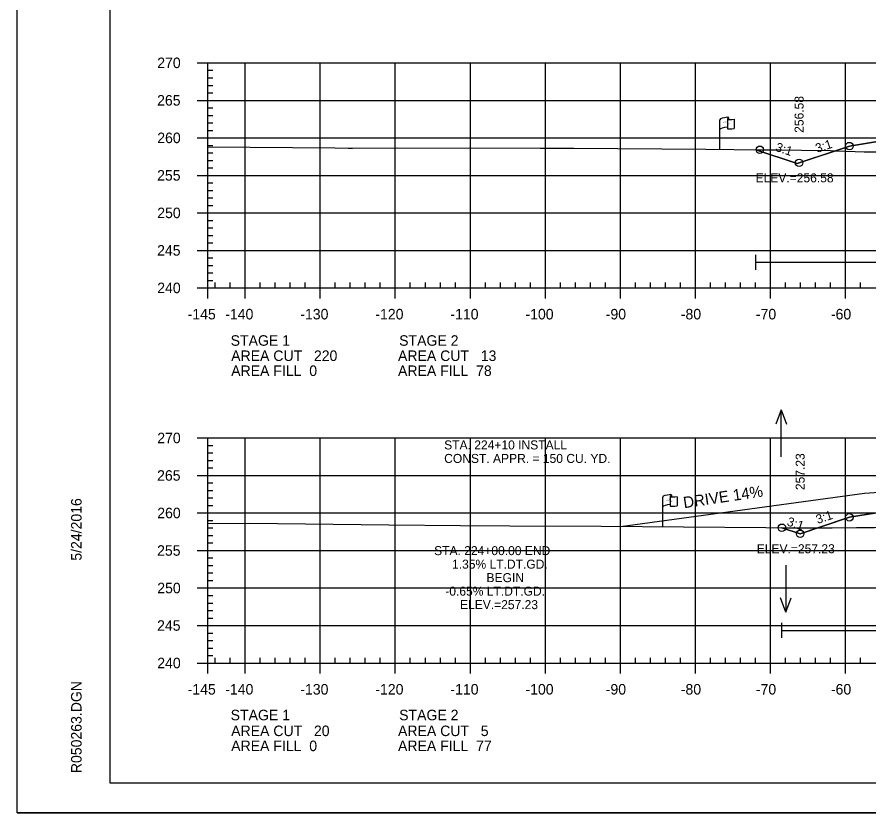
# Model space of a CAD drawing. Extents: x 1365647 to 1367999, y 387113 to 400173.
# Drawn here: x 1365723.7 to 1365837.2, y 391639.5 to 391745.6 of the extents above; entities that cross this region are included whole.
import ezdxf

# ---------------------------------------------------------------- set-up
doc = ezdxf.new("R2010")
doc.units = 0
for name, color, linetype in [('E_Existing ROW', 7, 'Continuous'), ('R_Axis', 7, 'Continuous'), ('R_Axis Annot', 7, 'Continuous'), ('R_Border', 7, 'Continuous'), ('R_Border Notes', 7, 'Continuous'), ('R_Contours', 7, 'Continuous'), ('R_Draft', 7, 'Continuous'), ('R_Drive', 7, 'Continuous'), ('R_Exist Surface', 7, 'Continuous'), ('R_Fin Surface', 7, 'Continuous'), ('R_Fin Surface Annot', 7, 'Continuous'), ('R_Grid', 7, 'Continuous'), ('R_No Plot', 7, 'Continuous'), ('R_Proposed Const Limits', 7, 'Continuous'), ('R_Water', 7, 'Continuous'), ('R_Water Annot', 7, 'Continuous')]:
    doc.layers.add(name, color=color, linetype=linetype)

msp = doc.modelspace()

# ---------------------------------------------------------------- linework, layer by layer
at = {"layer": 'E_Existing ROW'}
for p, q in [((1365817.33, 391727.95), (1365817.33, 391731.9)), ((1365818.33, 391731.99), (1365818.33, 391731.98)), ((1365818.33, 391731.98), (1365818.33, 391730.75)), ((1365818.49, 391732.15), (1365818.49, 391731.91)), ((1365819.26, 391731.96), (1365819.26, 391730.72)), ((1365809.72, 391677.65), (1365809.72, 391681.6)), ((1365810.71, 391681.69), (1365810.71, 391681.68)), ((1365810.71, 391681.68), (1365810.71, 391680.45)), ((1365810.88, 391681.85), (1365810.88, 391681.61)), ((1365811.65, 391681.65), (1365811.65, 391680.41))]:
    msp.add_line(p, q, dxfattribs=at)
for centre, radius, start, end in [((1365818.41, 391731.99), 0.078, 88.6458, 274.2828), ((1365818.42, 391732.15), 0.0783, 263.0712, 93.9564), ((1365818.41, 391730.75), 0.0783, 180, 273.9564), ((1365810.79, 391681.69), 0.078, 88.6458, 274.2828), ((1365810.8, 391681.85), 0.0783, 263.0712, 93.9564), ((1365810.79, 391680.45), 0.0783, 180, 273.9564)]:
    msp.add_arc(centre, radius, start, end, dxfattribs=at)
for centre, major_axis, ratio, start_param, end_param in [((1365818.91, 391731.94), (-1.58, -0.04), 0.19887, 5.030368, 6.283185), ((1365819.62, 391732.06), (-1.23, -0.13), 0.052933, 0.159456, 1.268315), ((1365818.91, 391730.62), (-1.58, -0.04), 0.19887, 5.083035, 6.194897), ((1365819.62, 391730.82), (-1.23, -0.13), 0.052933, 0.159456, 1.268315), ((1365811.3, 391681.64), (-1.58, -0.04), 0.19887, 5.030368, 6.283185), ((1365812.01, 391681.76), (-1.23, -0.13), 0.052933, 0.159456, 1.268315), ((1365811.3, 391680.32), (-1.58, -0.04), 0.19887, 5.083035, 6.194897), ((1365812.01, 391680.52), (-1.23, -0.13), 0.052933, 0.159456, 1.268315)]:
    msp.add_ellipse(centre, major_axis=major_axis, ratio=ratio, start_param=start_param, end_param=end_param, dxfattribs=at)
at = {"layer": 'R_Axis'}
for p, q in [((1365747.69, 391739.48), (1365749.09, 391739.48)), ((1365749.09, 391709.48), (1365749.09, 391739.48)), ((1365749.09, 391738.48), (1365749.79, 391738.48)), ((1365749.09, 391737.48), (1365749.79, 391737.48)), ((1365749.09, 391736.48), (1365749.79, 391736.48)), ((1365749.09, 391735.48), (1365749.79, 391735.48)), ((1365747.69, 391734.48), (1365749.09, 391734.48)), ((1365749.09, 391733.48), (1365749.79, 391733.48)), ((1365749.09, 391732.48), (1365749.79, 391732.48)), ((1365749.09, 391731.48), (1365749.79, 391731.48)), ((1365749.09, 391730.48), (1365749.79, 391730.48)), ((1365747.69, 391729.48), (1365749.09, 391729.48)), ((1365749.09, 391728.48), (1365749.79, 391728.48)), ((1365749.09, 391727.48), (1365749.79, 391727.48)), ((1365749.09, 391726.48), (1365749.79, 391726.48)), ((1365749.09, 391725.48), (1365749.79, 391725.48)), ((1365747.69, 391724.48), (1365749.09, 391724.48)), ((1365749.09, 391723.48), (1365749.79, 391723.48)), ((1365749.09, 391722.48), (1365749.79, 391722.48)), ((1365749.09, 391721.48), (1365749.79, 391721.48)), ((1365749.09, 391720.48), (1365749.79, 391720.48)), ((1365747.69, 391719.48), (1365749.09, 391719.48)), ((1365749.09, 391718.48), (1365749.79, 391718.48)), ((1365749.09, 391717.48), (1365749.79, 391717.48)), ((1365749.09, 391716.48), (1365749.79, 391716.48)), ((1365749.09, 391715.48), (1365749.79, 391715.48)), ((1365747.69, 391714.48), (1365749.09, 391714.48)), ((1365749.09, 391713.48), (1365749.79, 391713.48)), ((1365749.09, 391712.48), (1365749.79, 391712.48)), ((1365749.09, 391711.48), (1365749.79, 391711.48)), ((1365749.09, 391710.48), (1365749.79, 391710.48)), ((1365749.09, 391709.48), (1365749.09, 391710.18)), ((1365750.09, 391709.48), (1365750.09, 391710.18)), ((1365752.09, 391709.48), (1365752.09, 391710.18)), ((1365756.09, 391709.48), (1365756.09, 391710.18)), ((1365758.09, 391709.48), (1365758.09, 391710.18)), ((1365760.09, 391709.48), (1365760.09, 391710.18)), ((1365762.09, 391709.48), (1365762.09, 391710.18)), ((1365766.09, 391709.48), (1365766.09, 391710.18)), ((1365768.09, 391709.48), (1365768.09, 391710.18)), ((1365770.09, 391709.48), (1365770.09, 391710.18)), ((1365772.09, 391709.48), (1365772.09, 391710.18)), ((1365776.09, 391709.48), (1365776.09, 391710.18)), ((1365778.09, 391709.48), (1365778.09, 391710.18)), ((1365780.09, 391709.48), (1365780.09, 391710.18)), ((1365782.09, 391709.48), (1365782.09, 391710.18)), ((1365786.09, 391709.48), (1365786.09, 391710.18)), ((1365788.09, 391709.48), (1365788.09, 391710.18)), ((1365790.09, 391709.48), (1365790.09, 391710.18)), ((1365792.09, 391709.48), (1365792.09, 391710.18)), ((1365796.09, 391709.48), (1365796.09, 391710.18)), ((1365798.09, 391709.48), (1365798.09, 391710.18)), ((1365800.09, 391709.48), (1365800.09, 391710.18)), ((1365802.09, 391709.48), (1365802.09, 391710.18)), ((1365806.09, 391709.48), (1365806.09, 391710.18)), ((1365808.09, 391709.48), (1365808.09, 391710.18)), ((1365810.09, 391709.48), (1365810.09, 391710.18)), ((1365812.09, 391709.48), (1365812.09, 391710.18)), ((1365816.09, 391709.48), (1365816.09, 391710.18)), ((1365818.09, 391709.48), (1365818.09, 391710.18)), ((1365820.09, 391709.48), (1365820.09, 391710.18)), ((1365822.09, 391709.48), (1365822.09, 391710.18)), ((1365826.09, 391709.48), (1365826.09, 391710.18)), ((1365828.09, 391709.48), (1365828.09, 391710.18)), ((1365830.09, 391709.48), (1365830.09, 391710.18)), ((1365832.09, 391709.48), (1365832.09, 391710.18)), ((1365836.09, 391709.48), (1365836.09, 391710.18)), ((1365747.69, 391709.48), (1365749.09, 391709.48)), ((1365749.09, 391709.48), (1366039.09, 391709.48)), ((1365749.09, 391708.08), (1365749.09, 391709.48)), ((1365754.09, 391708.08), (1365754.09, 391709.48)), ((1365764.09, 391708.08), (1365764.09, 391709.48)), ((1365774.09, 391708.08), (1365774.09, 391709.48)), ((1365784.09, 391708.08), (1365784.09, 391709.48)), ((1365794.09, 391708.08), (1365794.09, 391709.48)), ((1365804.09, 391708.08), (1365804.09, 391709.48)), ((1365814.09, 391708.08), (1365814.09, 391709.48)), ((1365824.09, 391708.08), (1365824.09, 391709.48)), ((1365834.09, 391708.08), (1365834.09, 391709.48)), ((1365747.69, 391689.48), (1365749.09, 391689.48)), ((1365749.09, 391659.48), (1365749.09, 391689.48)), ((1365749.09, 391688.48), (1365749.79, 391688.48)), ((1365749.09, 391687.48), (1365749.79, 391687.48)), ((1365749.09, 391686.48), (1365749.79, 391686.48)), ((1365749.09, 391685.48), (1365749.79, 391685.48)), ((1365747.69, 391684.48), (1365749.09, 391684.48)), ((1365749.09, 391683.48), (1365749.79, 391683.48)), ((1365749.09, 391682.48), (1365749.79, 391682.48)), ((1365749.09, 391681.48), (1365749.79, 391681.48)), ((1365749.09, 391680.48), (1365749.79, 391680.48)), ((1365747.69, 391679.48), (1365749.09, 391679.48)), ((1365749.09, 391678.48), (1365749.79, 391678.48)), ((1365749.09, 391677.48), (1365749.79, 391677.48)), ((1365749.09, 391676.48), (1365749.79, 391676.48)), ((1365749.09, 391675.48), (1365749.79, 391675.48)), ((1365747.69, 391674.48), (1365749.09, 391674.48)), ((1365749.09, 391673.48), (1365749.79, 391673.48)), ((1365749.09, 391672.48), (1365749.79, 391672.48)), ((1365749.09, 391671.48), (1365749.79, 391671.48)), ((1365749.09, 391670.48), (1365749.79, 391670.48)), ((1365747.69, 391669.48), (1365749.09, 391669.48)), ((1365749.09, 391668.48), (1365749.79, 391668.48)), ((1365749.09, 391667.48), (1365749.79, 391667.48)), ((1365749.09, 391666.48), (1365749.79, 391666.48)), ((1365749.09, 391665.48), (1365749.79, 391665.48)), ((1365747.69, 391664.48), (1365749.09, 391664.48)), ((1365749.09, 391663.48), (1365749.79, 391663.48)), ((1365749.09, 391662.48), (1365749.79, 391662.48)), ((1365749.09, 391661.48), (1365749.79, 391661.48)), ((1365749.09, 391660.48), (1365749.79, 391660.48)), ((1365749.09, 391659.48), (1365749.09, 391660.18)), ((1365750.09, 391659.48), (1365750.09, 391660.18)), ((1365752.09, 391659.48), (1365752.09, 391660.18)), ((1365756.09, 391659.48), (1365756.09, 391660.18)), ((1365758.09, 391659.48), (1365758.09, 391660.18)), ((1365760.09, 391659.48), (1365760.09, 391660.18)), ((1365762.09, 391659.48), (1365762.09, 391660.18)), ((1365766.09, 391659.48), (1365766.09, 391660.18)), ((1365768.09, 391659.48), (1365768.09, 391660.18)), ((1365770.09, 391659.48), (1365770.09, 391660.18)), ((1365772.09, 391659.48), (1365772.09, 391660.18)), ((1365776.09, 391659.48), (1365776.09, 391660.18)), ((1365778.09, 391659.48), (1365778.09, 391660.18)), ((1365780.09, 391659.48), (1365780.09, 391660.18)), ((1365782.09, 391659.48), (1365782.09, 391660.18)), ((1365786.09, 391659.48), (1365786.09, 391660.18)), ((1365788.09, 391659.48), (1365788.09, 391660.18)), ((1365790.09, 391659.48), (1365790.09, 391660.18)), ((1365792.09, 391659.48), (1365792.09, 391660.18)), ((1365796.09, 391659.48), (1365796.09, 391660.18)), ((1365798.09, 391659.48), (1365798.09, 391660.18)), ((1365800.09, 391659.48), (1365800.09, 391660.18)), ((1365802.09, 391659.48), (1365802.09, 391660.18)), ((1365806.09, 391659.48), (1365806.09, 391660.18)), ((1365808.09, 391659.48), (1365808.09, 391660.18)), ((1365810.09, 391659.48), (1365810.09, 391660.18)), ((1365812.09, 391659.48), (1365812.09, 391660.18)), ((1365816.09, 391659.48), (1365816.09, 391660.18)), ((1365818.09, 391659.48), (1365818.09, 391660.18)), ((1365820.09, 391659.48), (1365820.09, 391660.18)), ((1365822.09, 391659.48), (1365822.09, 391660.18)), ((1365826.09, 391659.48), (1365826.09, 391660.18)), ((1365828.09, 391659.48), (1365828.09, 391660.18)), ((1365830.09, 391659.48), (1365830.09, 391660.18)), ((1365832.09, 391659.48), (1365832.09, 391660.18)), ((1365836.09, 391659.48), (1365836.09, 391660.18)), ((1365747.69, 391659.48), (1365749.09, 391659.48)), ((1365749.09, 391659.48), (1366039.09, 391659.48)), ((1365749.09, 391658.08), (1365749.09, 391659.48)), ((1365754.09, 391658.08), (1365754.09, 391659.48)), ((1365764.09, 391658.08), (1365764.09, 391659.48)), ((1365774.09, 391658.08), (1365774.09, 391659.48)), ((1365784.09, 391658.08), (1365784.09, 391659.48)), ((1365794.09, 391658.08), (1365794.09, 391659.48)), ((1365804.09, 391658.08), (1365804.09, 391659.48)), ((1365814.09, 391658.08), (1365814.09, 391659.48)), ((1365824.09, 391658.08), (1365824.09, 391659.48)), ((1365834.09, 391658.08), (1365834.09, 391659.48))]:
    msp.add_line(p, q, dxfattribs=at)
at = {"layer": 'R_Border'}
for p, q in [((1365736.09, 391643.48), (1365736.09, 391848.94)), ((1365736.09, 391643.48), (1365736.09, 391643.48)), ((1366052.27, 391643.48), (1365736.09, 391643.48))]:
    msp.add_line(p, q, dxfattribs=at)
at = {"layer": 'R_Contours'}
for points in [[(1365832.72, 391727.75), (1365834.15, 391727.7), (1365836.57, 391727.61), (1365841.76, 391727.62), (1365842.71, 391727.61), (1365844.18, 391727.57), (1365854.56, 391727.2), (1365859.19, 391727.18), (1365863.77, 391727.08), (1365863.81, 391727.09), (1365864.83, 391727.26), (1365868.52, 391728.02), (1365869.44, 391728.24), (1365872.47, 391729.03), (1365862.59, 391729.99), (1365841.78, 391729.58), (1365834.59, 391728.38)], [(1365822.13, 391727.9), (1365822.98, 391727.89), (1365825.42, 391727.9), (1365828.19, 391727.82), (1365832.09, 391727.78), (1365832.72, 391727.75), (1365827.63, 391726.06)], [(1365830.4, 391677.5), (1365832.28, 391677.51), (1365835.52, 391677.53), (1365837.92, 391677.55), (1365840.66, 391677.57), (1365849.32, 391677.89), (1365850.29, 391677.93), (1365855.76, 391678), (1365859.3, 391678.04), (1365859.64, 391678.05), (1365860.43, 391678.13), (1365863.23, 391678.35), (1365864.65, 391678.53), (1365866.33, 391678.76), (1365869.69, 391679.29), (1365871.65, 391679.62), (1365862.59, 391680.51), (1365841.78, 391680.09), (1365834.59, 391678.9)], [(1365825.6, 391677.51), (1365827.31, 391677.49), (1365828.35, 391677.49), (1365830.4, 391677.5), (1365828.03, 391676.71)]]:
    msp.add_lwpolyline(points, close=True, dxfattribs=at)
at = {"layer": 'R_Drive'}
for p, q in [((1365836.61, 391682.14), (1365846.59, 391682.76)), ((1365804.09, 391677.69), (1365836.61, 391682.14))]:
    msp.add_line(p, q, dxfattribs=at)
at = {"layer": 'R_Exist Surface'}
for points in [[(1365749.09, 391728.29), (1365766.02, 391728.13), (1365767.8, 391728.11), (1365768.39, 391728.12), (1365774.37, 391728.16), (1365793.39, 391728.12), (1365797.88, 391728.11), (1365815.48, 391727.97), (1365822.98, 391727.89), (1365825.42, 391727.9), (1365828.19, 391727.82), (1365832.09, 391727.78), (1365834.15, 391727.7), (1365836.57, 391727.61), (1365841.76, 391727.62)], [(1365749.09, 391678.09), (1365754.7, 391678.12), (1365773.23, 391677.9), (1365782.76, 391677.81), (1365789.37, 391677.77), (1365801.53, 391677.71), (1365823.45, 391677.54), (1365827.31, 391677.49), (1365828.35, 391677.49), (1365832.28, 391677.51), (1365835.52, 391677.53), (1365837.92, 391677.55)]]:
    msp.add_lwpolyline(points, dxfattribs=at)
at = {"layer": 'R_Fin Surface'}
for points in [[(1365822.13, 391727.9), (1365827.63, 391726.06), (1365834.59, 391728.38), (1365841.78, 391729.58), (1365856.59, 391732.05), (1365862.59, 391731.46), (1365864.59, 391731.26), (1365894.09, 391728.37), (1365923.59, 391725.48), (1365925.59, 391725.28), (1365931.59, 391724.7), (1365953.01, 391721.13), (1365953.59, 391721.03), (1365960.86, 391718.61), (1365983.15, 391726.04)], [(1365825.6, 391677.51), (1365828.03, 391676.71), (1365834.59, 391678.9), (1365841.78, 391680.09), (1365856.59, 391682.56), (1365862.59, 391681.97), (1365864.59, 391681.78), (1365894.09, 391678.89), (1365923.59, 391676), (1365925.59, 391675.8), (1365931.59, 391675.21), (1365953.01, 391671.64), (1365953.59, 391671.55), (1365957.05, 391670.39), (1365972.56, 391675.56)]]:
    msp.add_lwpolyline(points, dxfattribs=at)
at = {"layer": 'R_Grid'}
for p, q in [((1365749.09, 391739.48), (1366039.09, 391739.48)), ((1365749.09, 391709.48), (1365749.09, 391739.48)), ((1365754.09, 391709.48), (1365754.09, 391739.48)), ((1365764.09, 391709.48), (1365764.09, 391739.48)), ((1365774.09, 391709.48), (1365774.09, 391739.48)), ((1365784.09, 391709.48), (1365784.09, 391739.48)), ((1365794.09, 391709.48), (1365794.09, 391739.48)), ((1365804.09, 391709.48), (1365804.09, 391739.48)), ((1365814.09, 391709.48), (1365814.09, 391739.48)), ((1365824.09, 391709.48), (1365824.09, 391739.48)), ((1365834.09, 391709.48), (1365834.09, 391739.48)), ((1365749.09, 391734.48), (1366039.09, 391734.48)), ((1365749.09, 391729.48), (1366039.09, 391729.48)), ((1365749.09, 391724.48), (1366039.09, 391724.48)), ((1365749.09, 391719.48), (1366039.09, 391719.48)), ((1365749.09, 391714.48), (1366039.09, 391714.48)), ((1365749.09, 391709.48), (1366039.09, 391709.48)), ((1365749.09, 391689.48), (1366039.09, 391689.48)), ((1365749.09, 391659.48), (1365749.09, 391689.48)), ((1365754.09, 391659.48), (1365754.09, 391689.48)), ((1365764.09, 391659.48), (1365764.09, 391689.48)), ((1365774.09, 391659.48), (1365774.09, 391689.48)), ((1365784.09, 391659.48), (1365784.09, 391689.48)), ((1365794.09, 391659.48), (1365794.09, 391689.48)), ((1365804.09, 391659.48), (1365804.09, 391689.48)), ((1365814.09, 391659.48), (1365814.09, 391689.48)), ((1365824.09, 391659.48), (1365824.09, 391689.48)), ((1365834.09, 391659.48), (1365834.09, 391689.48)), ((1365749.09, 391684.48), (1366039.09, 391684.48)), ((1365749.09, 391679.48), (1366039.09, 391679.48)), ((1365749.09, 391674.48), (1366039.09, 391674.48)), ((1365749.09, 391669.48), (1366039.09, 391669.48)), ((1365749.09, 391664.48), (1366039.09, 391664.48)), ((1365749.09, 391659.48), (1366039.09, 391659.48))]:
    msp.add_line(p, q, dxfattribs=at)
at = {"layer": 'R_No Plot'}
msp.add_line((1365723.69, 391639.5), (1366057.03, 391639.5), dxfattribs=at)
msp.add_lwpolyline([(1365723.69, 391852.83), (1366057.03, 391852.83), (1366057.03, 391639.49), (1365723.69, 391639.49)], close=True, dxfattribs=at)
for centre in [(1365834.59, 391728.38), (1365834.59, 391728.38), (1365834.59, 391728.38), (1365834.59, 391728.38), (1365834.59, 391728.38), (1365822.66, 391727.89), (1365822.66, 391727.89), (1365827.89, 391726.15), (1365827.89, 391726.15), (1365834.59, 391678.9), (1365834.59, 391678.9), (1365834.59, 391678.9), (1365834.59, 391678.9), (1365834.59, 391678.9), (1365825.6, 391677.51), (1365825.6, 391677.51), (1365828.03, 391676.71), (1365828.03, 391676.71)]:
    msp.add_circle(centre, 0.5, dxfattribs=at)
at = {"layer": 'R_Proposed Const Limits'}
msp.add_lwpolyline([(1365828.03, 391676.71), (1365825.6, 391677.51)], dxfattribs=at)
at = {"layer": 'R_Water'}
for p, q in [((1365822.13, 391711.9), (1365822.13, 391713.9)), ((1365822.13, 391712.9), (1365880.68, 391712.9)), ((1365825.6, 391662.83), (1365825.6, 391664.83)), ((1365825.6, 391663.83), (1365880.25, 391663.83))]:
    msp.add_line(p, q, dxfattribs=at)
at = {"layer": 'R_Water Annot'}
for p, q in [((1365825.51, 391693.24), (1365824.81, 391691.31)), ((1365825.51, 391686.95), (1365825.51, 391693.24)), ((1365825.51, 391693.24), (1365826.21, 391691.31)), ((1365826.13, 391672.54), (1365826.13, 391666.25)), ((1365826.13, 391666.25), (1365825.43, 391668.18)), ((1365826.13, 391666.25), (1365826.83, 391668.18))]:
    msp.add_line(p, q, dxfattribs=at)

# ---------------------------------------------------------------- texts
at = {"layer": 'E_Existing ROW'}
for s, height, rotation, p in [('R ', 0.2, 9.9884, (1365817.85, 391731.4)), (' O', 0.2, 9.9884, (1365818, 391731.45)), ('W', 0.2, 351.1788, (1365818.33, 391731.28)), ('DWB 11-9-07', 0.001, 90, (1365818.49, 391731.91)), ('DWB 11-9-07', 0.001, 5.0717, (1365819.25, 391730.72)), ('DWB 11-9-07', 0.001, 90, (1365817.33, 391727.95)), ('R ', 0.2, 9.9884, (1365810.24, 391681.1)), (' O', 0.2, 9.9884, (1365810.38, 391681.14)), ('W', 0.2, 351.1788, (1365810.71, 391680.97)), ('DWB 11-9-07', 0.001, 90, (1365810.88, 391681.61)), ('DWB 11-9-07', 0.001, 5.0717, (1365811.64, 391680.41)), ('DWB 11-9-07', 0.001, 90, (1365809.72, 391677.65))]:
    msp.add_text(s, height=height, rotation=rotation, dxfattribs=at).set_placement(p)
at = {"layer": 'R_Axis Annot'}
for s, p in [('270', (1365742.37, 391738.78)), ('265', (1365742.35, 391733.78)), ('260', (1365742.37, 391728.78)), ('255', (1365742.35, 391723.78)), ('250', (1365742.37, 391718.78)), ('245', (1365742.35, 391713.78)), ('240', (1365742.37, 391708.78)), ('-145', (1365746.42, 391705.28)), ('-140', (1365751.43, 391705.28)), ('-130', (1365761.43, 391705.28)), ('-120', (1365771.43, 391705.28)), ('-110', (1365781.43, 391705.28)), ('-100', (1365791.43, 391705.28)), ('-90', (1365802.13, 391705.28)), ('-80', (1365812.13, 391705.28)), ('-70', (1365822.13, 391705.28)), ('-60', (1365832.13, 391705.28)), ('STAGE 1', (1365752.15, 391701.77)), ('STAGE 2', (1365774.6, 391701.77)), ('AREA CUT   220', (1365752.22, 391699.74)), ('AREA CUT   13', (1365774.45, 391699.74)), ('AREA FILL  0', (1365752.22, 391697.74)), ('AREA FILL  78', (1365774.45, 391697.74)), ('270', (1365742.37, 391688.78)), ('265', (1365742.35, 391683.78)), ('260', (1365742.37, 391678.78)), ('255', (1365742.35, 391673.78)), ('250', (1365742.37, 391668.78)), ('245', (1365742.35, 391663.78)), ('240', (1365742.37, 391658.78)), ('-145', (1365746.42, 391655.28)), ('-140', (1365751.43, 391655.28)), ('-130', (1365761.43, 391655.28)), ('-120', (1365771.43, 391655.28)), ('-110', (1365781.43, 391655.28)), ('-100', (1365791.43, 391655.28)), ('-90', (1365802.13, 391655.28)), ('-80', (1365812.13, 391655.28)), ('-70', (1365822.13, 391655.28)), ('-60', (1365832.13, 391655.28)), ('STAGE 1', (1365752.15, 391651.85)), ('STAGE 2', (1365774.6, 391651.85)), ('AREA CUT   20', (1365752.22, 391649.74)), ('AREA CUT   5', (1365774.45, 391649.74)), ('AREA FILL  0', (1365752.22, 391647.74)), ('AREA FILL  77', (1365774.45, 391647.74))]:
    msp.add_text(s, height=1.4, dxfattribs=at).set_placement(p)
at = {"layer": 'R_Border'}
for s, p in [('5/24/2016', (1365732.29, 391673.12)), ('R050263.DGN', (1365732.29, 391644.8))]:
    msp.add_text(s, height=1.4, rotation=90, dxfattribs=at).set_placement(p)
at = {"layer": 'R_Border Notes'}
for s, p in [('ELEV.=256.58', (1365822.09, 391723.55)), ('ELEV.=257.23', (1365822.25, 391674.11))]:
    msp.add_text(s, height=1.2, dxfattribs=at).set_placement(p)
at = {"layer": 'R_Draft'}
for s, p in [('STA. 224+10 INSTALL ', (1365780.6, 391687.95)), ('CONST. APPR. = 150 CU. YD.', (1365780.6, 391686.15))]:
    msp.add_text(s, height=1.2, rotation=360, dxfattribs=at).set_placement(p)
at = {"layer": 'R_Drive'}
msp.add_text('DRIVE 14%', height=1.5, rotation=8.437, dxfattribs=at).set_placement((1365812.57, 391680.11))
at = {"layer": 'R_Fin Surface Annot'}
for s, rotation, p in [('256.58', 90, (1365828.49, 391730.15)), ('3:1', 18.4349, (1365830.29, 391727.47)), ('3:1', 341.5651, (1365824.65, 391727.76)), ('257.23', 90, (1365828.63, 391682.53)), ('3:1', 341.5651, (1365826.18, 391677.85)), ('3:1', 18.4349, (1365830.36, 391678.01))]:
    msp.add_text(s, height=1.2, rotation=rotation, dxfattribs=at).set_placement(p)
at = {"layer": 'R_Water'}
for s, p in [('STA. 224+00.00 END', (1365779.26, 391673.86)), ('1.35% LT.DT.GD.', (1365781.65, 391672.06)), ('BEGIN', (1365786.24, 391670.26)), ('-0.65% LT.DT.GD.', (1365780.75, 391668.46)), ('ELEV.=257.23', (1365782.71, 391666.66))]:
    msp.add_text(s, height=1.2, dxfattribs=at).set_placement(p)

doc.saveas('drawing.dxf')
